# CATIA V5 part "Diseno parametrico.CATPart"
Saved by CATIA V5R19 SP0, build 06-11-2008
Part number: Diseno parametrico
Bounding box of the stored display mesh (mm): x -68.154 to 118.733, y -50 to 73.193, z 0 to 79.207
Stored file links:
  G:\Prácticas\0068\68_v5r19\Diseno parametrico.CATPart
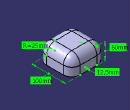
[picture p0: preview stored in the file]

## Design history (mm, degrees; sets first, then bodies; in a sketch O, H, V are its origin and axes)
Parameters
  Lado = 100 mm
Body1 (main body)
  Sketch1 on xy-plane, origin (0, 0, 0), H (1, 0, 0), V (0, 1, 0)
    line L1 (50, 50) -> (50, -50)
    line L2 (50, -50) -> (-50, -50)
    line L3 (-50, -50) -> (-50, 50)
    line L4 (-50, 50) -> (50, 50)
    length L1 = 100 {= Lado}
    length L2 = 100 {= Lado}
    vertical: L1 V, L3 V
    horizontal: L2 H, L4 H
    equidistance: L1 L3 O, L2 L4 O
  Pad1: profile Sketch1, direction (0, 0, 1), length 50 {= Sketch1.length(L2) /2}
  Fillet1: radius 25 {= Pad1.FirstLimit.Length /2}, on edge [face of Pad1 from Sketch1.L4 | face of Pad1 from Sketch1.L1]; edge [face of Pad1 from Sketch1.L3 | face of Pad1 from Sketch1.L4]; edge [face of Pad1 from Sketch1.L1 | face of Pad1 from Sketch1.L2]; edge [face of Pad1 from Sketch1.L2 | face of Pad1 from Sketch1.L3]; end face of Pad1
  Shell1: ExtOffset 0, IntOffset 12.5 {= Fillet1.Radius /2}, Face start face of Pad1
